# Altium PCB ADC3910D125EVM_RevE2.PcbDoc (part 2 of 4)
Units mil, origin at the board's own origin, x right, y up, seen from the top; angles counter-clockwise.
Board outline 4000 x 2716.54 mil, 6 copper layers (Top Layer, L2 GND, L3 PWR, L4 PWR, L5 GND, Bottom Layer), stack 60.99 mil thick; 318 components, 203 nets, 1298 pads, 559 vias.
Unrouted connection lines stored in the file: 5.
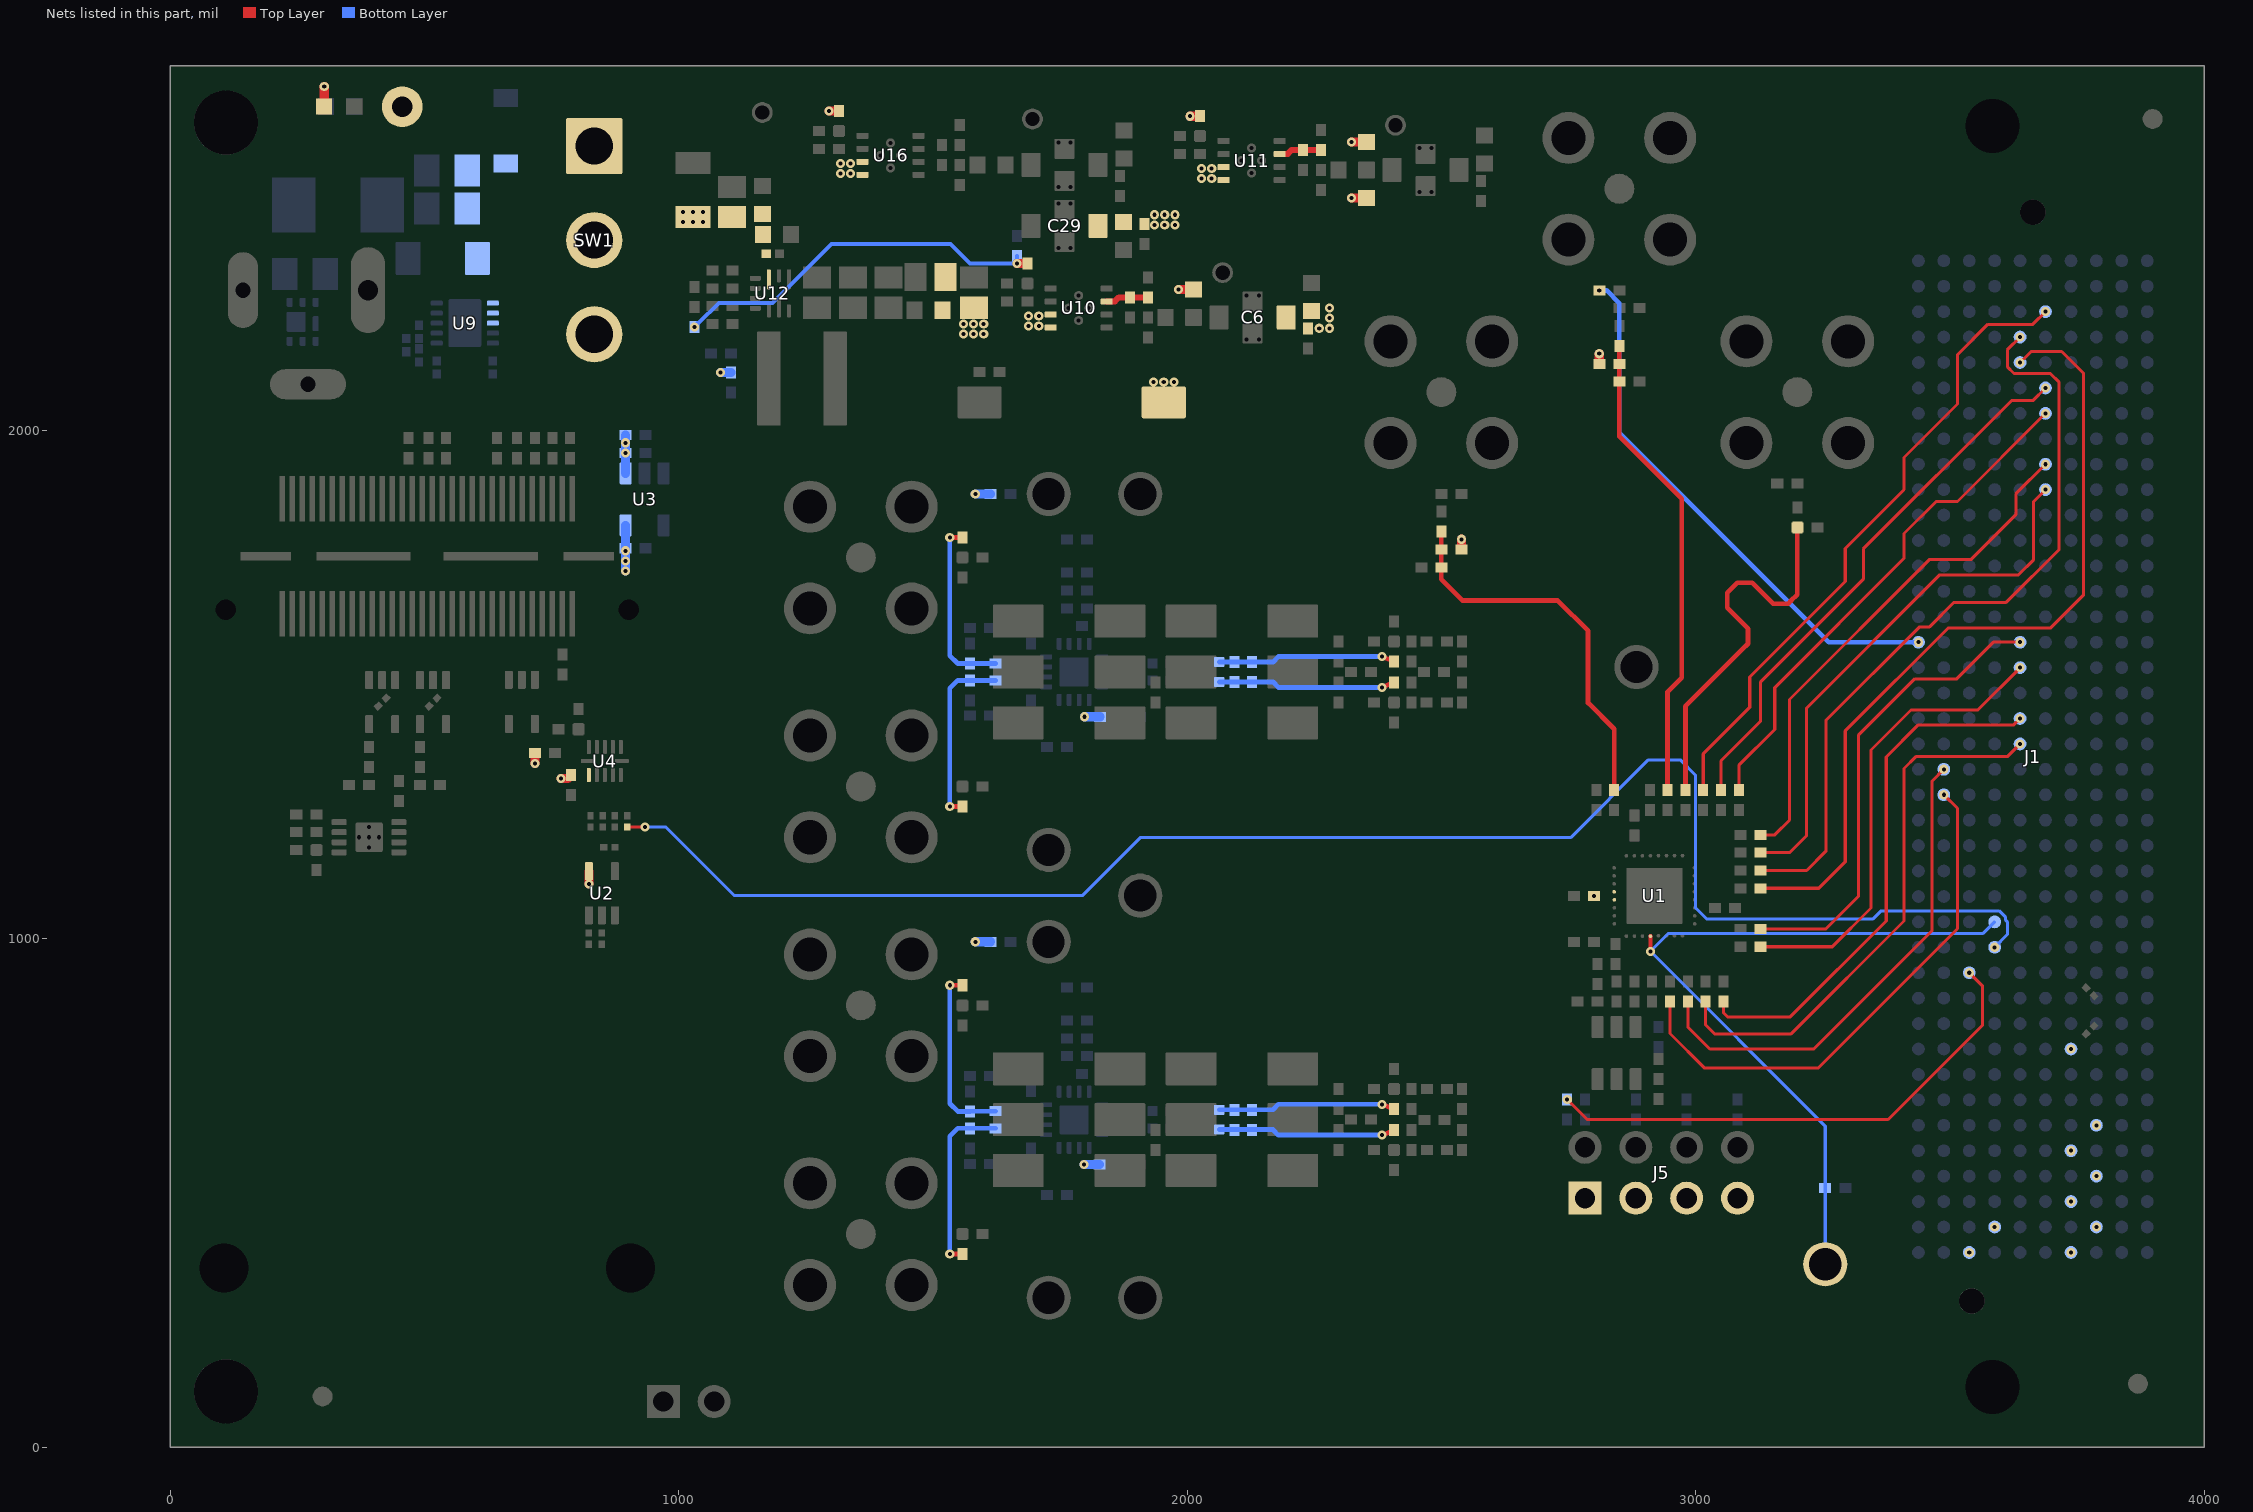
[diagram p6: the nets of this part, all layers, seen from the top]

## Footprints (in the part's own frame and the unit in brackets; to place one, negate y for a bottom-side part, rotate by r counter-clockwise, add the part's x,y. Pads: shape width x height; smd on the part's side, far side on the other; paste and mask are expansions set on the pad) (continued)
RSN0032B-MFG [mm]
  round 0.18 smd paste+0 mask+0: 1(-2.01,1.4) 2(-2.01,1) 3(-2.01,0.6) 4(-2.01,0.2) 5(-2,-0.2) 6(-2,-0.6) 7(-2,-1) 8(-2,-1.4) 9(-1.4,-2.01) 10(-1,-2.01) 11(-0.6,-2.01) 12(-0.2,-2.01) 13(0.2,-2) 14(0.6,-2) 15(1,-2) 16(1.4,-2) 17(2.01,-1.4) 18(2.01,-1) 19(2.01,-0.6) 20(2.01,-0.2) 21(2,0.2) 22(2,0.6) 23(2,1) 24(2,1.4) 25(1.4,2.01) 26(1,2.01) 27(0.6,2.01) 28(0.2,2.01) 29(-0.2,2) 30(-0.6,2) 31(-1,2) 32(-1.4,2)
  rrect4% 2.8x2.8 smd paste-1000 mask+0: 33(0,0)
  Top Layer region: -1.3,2.4 -1.3,1.7 -1.313,1.65 -1.35,1.613 -1.4,1.6 -1.4,1.6 -1.438,1.608 -1.471,1.629 -1.492,1.662 -1.5,1.7 -1.5,1.7 -1.5,2.4
  Top Layer region: -0.9,2.4 -0.9,1.7 -0.908,1.662 -0.929,1.629 -0.962,1.608 -1,1.6 -1,1.6 -1.038,1.608 -1.071,1.629 -1.092,1.662 -1.1,1.7 -1.1,1.7 -1.1,2.4
  Top Layer region: -0.5,2.4 -0.5,1.7 -0.508,1.662 -0.529,1.629 -0.562,1.608 -0.6,1.6 -0.6,1.6 -0.638,1.608 -0.671,1.629 -0.692,1.662 -0.7,1.7 -0.7,1.7 -0.7,2.4
  Top Layer region: -0.1,2.4 -0.1,1.7 -0.108,1.662 -0.129,1.629 -0.162,1.608 -0.2,1.6 -0.2,1.6 -0.238,1.608 -0.271,1.629 -0.292,1.662 -0.3,1.7 -0.3,1.7 -0.3,2.4
  Top Layer region: 0.3,2.4 0.3,1.7 0.292,1.662 0.271,1.629 0.238,1.608 0.2,1.6 0.2,1.6 0.162,1.608 0.129,1.629 0.108,1.662 0.1,1.7 0.1,1.7 0.1,2.4
  Top Layer region: 0.7,2.4 0.7,1.7 0.687,1.65 0.65,1.613 0.6,1.6 0.6,1.6 0.562,1.608 0.529,1.629 0.508,1.662 0.5,1.7 0.5,1.7 0.5,2.4
  Top Layer region: 1.1,2.4 1.1,1.7 1.092,1.662 1.071,1.629 1.038,1.608 1,1.6 1,1.6 0.962,1.608 0.929,1.629 0.908,1.662 0.9,1.7 0.9,1.7 0.9,2.4
  Top Layer region: 1.5,2.4 1.5,1.7 1.492,1.662 1.471,1.629 1.438,1.608 1.4,1.6 1.4,1.6 1.362,1.608 1.329,1.629 1.308,1.662 1.3,1.7 1.3,1.7 1.3,2.4
  Top Layer region: 1.3,-2.4 1.3,-1.7 1.308,-1.662 1.329,-1.629 1.362,-1.608 1.4,-1.6 1.4,-1.6 1.438,-1.608 1.471,-1.629 1.492,-1.662 1.5,-1.7 1.5,-1.7 1.5,-2.4
  Top Layer region: 0.9,-2.4 0.9,-1.7 0.908,-1.662 0.929,-1.629 0.962,-1.608 1,-1.6 1,-1.6 1.038,-1.608 1.071,-1.629 1.092,-1.662 1.1,-1.7 1.1,-1.7 1.1,-2.4
  Top Layer region: 0.5,-2.4 0.5,-1.7 0.508,-1.662 0.529,-1.629 0.562,-1.608 0.6,-1.6 0.6,-1.6 0.638,-1.608 0.671,-1.629 0.692,-1.662 0.7,-1.7 0.7,-1.7 0.7,-2.4
  Top Layer region: 0.1,-2.4 0.1,-1.7 0.108,-1.662 0.129,-1.629 0.162,-1.608 0.2,-1.6 0.2,-1.6 0.238,-1.608 0.271,-1.629 0.292,-1.662 0.3,-1.7 0.3,-1.7 0.3,-2.4
  Top Layer region: -0.3,-2.4 -0.3,-1.7 -0.292,-1.662 -0.271,-1.629 -0.238,-1.608 -0.2,-1.6 -0.2,-1.6 -0.162,-1.608 -0.129,-1.629 -0.108,-1.662 -0.1,-1.7 -0.1,-1.7 -0.1,-2.4
  Top Layer region: -0.7,-2.4 -0.7,-1.7 -0.692,-1.662 -0.671,-1.629 -0.638,-1.608 -0.6,-1.6 -0.6,-1.6 -0.562,-1.608 -0.529,-1.629 -0.508,-1.662 -0.5,-1.7 -0.5,-1.7 -0.5,-2.4
  Top Layer region: -1.1,-2.4 -1.1,-1.7 -1.092,-1.662 -1.071,-1.629 -1.038,-1.608 -1,-1.6 -1,-1.6 -0.962,-1.608 -0.929,-1.629 -0.908,-1.662 -0.9,-1.7 -0.9,-1.7 -0.9,-2.4
  Top Layer region: -1.5,-2.4 -1.5,-1.7 -1.492,-1.662 -1.471,-1.629 -1.438,-1.608 -1.4,-1.6 -1.4,-1.6 -1.362,-1.608 -1.329,-1.629 -1.308,-1.662 -1.3,-1.7 -1.3,-1.7 -1.3,-2.4
  Top Layer region: 2.4,1.3 1.7,1.3 1.662,1.308 1.629,1.329 1.608,1.362 1.6,1.4 1.6,1.4 1.608,1.438 1.629,1.471 1.662,1.492 1.7,1.5 1.7,1.5 2.4,1.5
  Top Layer region: 2.4,0.9 1.7,0.9 1.662,0.908 1.629,0.929 1.608,0.962 1.6,1 1.6,1 1.608,1.038 1.629,1.071 1.662,1.092 1.7,1.1 1.7,1.1 2.4,1.1
  Top Layer region: 2.4,0.5 1.7,0.5 1.662,0.508 1.629,0.529 1.608,0.562 1.6,0.6 1.6,0.6 1.608,0.638 1.629,0.671 1.662,0.692 1.7,0.7 1.7,0.7 2.4,0.7
  Top Layer region: 2.4,0.1 1.7,0.1 1.662,0.108 1.629,0.129 1.608,0.162 1.6,0.2 1.6,0.2 1.608,0.238 1.629,0.271 1.662,0.292 1.7,0.3 1.7,0.3 2.4,0.3
  Top Layer region: 2.4,-0.3 1.7,-0.3 1.662,-0.292 1.629,-0.271 1.608,-0.238 1.6,-0.2 1.6,-0.2 1.608,-0.162 1.629,-0.129 1.662,-0.108 1.7,-0.1 1.7,-0.1 2.4,-0.1
  Top Layer region: 2.4,-0.7 1.7,-0.7 1.662,-0.692 1.629,-0.671 1.608,-0.638 1.6,-0.6 1.6,-0.6 1.608,-0.562 1.629,-0.529 1.662,-0.508 1.7,-0.5 1.7,-0.5 2.4,-0.5
  Top Layer region: 2.4,-1.1 1.7,-1.1 1.662,-1.092 1.629,-1.071 1.608,-1.038 1.6,-1 1.6,-1 1.608,-0.962 1.629,-0.929 1.662,-0.908 1.7,-0.9 1.7,-0.9 2.4,-0.9
  Top Layer region: 2.4,-1.5 1.7,-1.5 1.662,-1.492 1.629,-1.471 1.608,-1.438 1.6,-1.4 1.6,-1.4 1.608,-1.362 1.629,-1.329 1.662,-1.308 1.7,-1.3 1.7,-1.3 2.4,-1.3
  Top Layer region: -2.4,-1.3 -1.7,-1.3 -1.662,-1.308 -1.629,-1.329 -1.608,-1.362 -1.6,-1.4 -1.6,-1.4 -1.613,-1.45 -1.65,-1.487 -1.7,-1.5 -1.7,-1.5 -2.4,-1.5
  Top Layer region: -2.4,-0.9 -1.7,-0.9 -1.662,-0.908 -1.629,-0.929 -1.608,-0.962 -1.6,-1 -1.6,-1 -1.608,-1.038 -1.629,-1.071 -1.662,-1.092 -1.7,-1.1 -1.7,-1.1 -2.4,-1.1
  Top Layer region: -2.4,-0.5 -1.7,-0.5 -1.662,-0.508 -1.629,-0.529 -1.608,-0.562 -1.6,-0.6 -1.6,-0.6 -1.608,-0.638 -1.629,-0.671 -1.662,-0.692 -1.7,-0.7 -1.7,-0.7 -2.4,-0.7
  Top Layer region: -2.4,-0.1 -1.7,-0.1 -1.662,-0.108 -1.629,-0.129 -1.608,-0.162 -1.6,-0.2 -1.6,-0.2 -1.608,-0.238 -1.629,-0.271 -1.662,-0.292 -1.7,-0.3 -1.7,-0.3 -2.4,-0.3
  Top Layer region: -2.4,0.3 -1.7,0.3 -1.662,0.292 -1.629,0.271 -1.608,0.238 -1.6,0.2 -1.6,0.2 -1.608,0.162 -1.629,0.129 -1.662,0.108 -1.7,0.1 -1.7,0.1 -2.4,0.1
  Top Layer region: -2.4,0.7 -1.7,0.7 -1.662,0.692 -1.629,0.671 -1.608,0.638 -1.6,0.6 -1.6,0.6 -1.608,0.562 -1.629,0.529 -1.662,0.508 -1.7,0.5 -1.7,0.5 -2.4,0.5
  Top Layer region: -2.4,1.1 -1.7,1.1 -1.662,1.092 -1.629,1.071 -1.608,1.038 -1.6,1 -1.6,1 -1.608,0.962 -1.629,0.929 -1.662,0.908 -1.7,0.9 -1.7,0.9 -2.4,0.9
  Top Layer region: -2.4,1.5 -1.7,1.5 -1.662,1.492 -1.629,1.471 -1.608,1.438 -1.6,1.4 -1.6,1.4 -1.608,1.362 -1.629,1.329 -1.662,1.308 -1.7,1.3 -1.7,1.3 -2.4,1.3
  silkscreen extent -3.1,-2.07 2.07,2.07, body extent -2.5,-2.5 2.5,2.5, height 0.25
RUT0012A [mm] "QFN, 12-Leads, Body 1.7x2mm, Pitch 0.4mm, TI Recommended"
  rrect50% 0.7x0.2 smd mask+0.05: 1(-0.7,0.8) 2(-0.7,0.4) 3(-0.7,0) 4(-0.7,-0.4) 5(-0.7,-0.8) 7(0.7,-0.8) 8(0.7,-0.4) 9(0.7,0) 10(0.7,0.4) 11(0.7,0.8)
  rrect50% 0.2x0.7 smd mask+0.05: 6(0,-0.85) 12(0,0.85)
  silkscreen extent -0.9,-1.2 0.9,1.2, body extent -0.85,-1 0.85,1, height 0.55
SAMTEC_ASP-134488-01 [mm]
  round 0.64 smd far side paste+0.125: A1(24.79,-5.715) A2(23.52,-5.715) A3(22.25,-5.715) A4(20.98,-5.715) A5(19.71,-5.715) A6(18.44,-5.715) A7(17.17,-5.715) A8(15.9,-5.715) A9(14.63,-5.715) A10(13.36,-5.715) A11(12.09,-5.715) A12(10.82,-5.715) A13(9.55,-5.715) A14(8.28,-5.715) A15(7.01,-5.715) A16(5.74,-5.715) A17(4.47,-5.715) A18(3.2,-5.715) A19(1.93,-5.715) A20(0.66,-5.715) A21(-0.61,-5.715) A22(-1.88,-5.715) A23(-3.15,-5.715) A24(-4.42,-5.715) A25(-5.69,-5.715) A26(-6.96,-5.715) A27(-8.23,-5.715) A28(-9.5,-5.715) A29(-10.77,-5.715) A30(-12.04,-5.715) A31(-13.31,-5.715) A32(-14.58,-5.715) A33(-15.85,-5.715) A34(-17.12,-5.715) A35(-18.39,-5.715) A36(-19.66,-5.715) A37(-20.93,-5.715) A38(-22.2,-5.715) A39(-23.47,-5.715) A40(-24.74,-5.715) B1(24.79,-4.445) B2(23.52,-4.445) B3(22.25,-4.445) B4(20.98,-4.445) B5(19.71,-4.445) B6(18.44,-4.445) B7(17.17,-4.445) B8(15.9,-4.445) B9(14.63,-4.445) B10(13.36,-4.445) B11(12.09,-4.445) B12(10.82,-4.445) B13(9.55,-4.445) B14(8.28,-4.445) B15(7.01,-4.445) B16(5.74,-4.445) B17(4.47,-4.445) B18(3.2,-4.445) B19(1.93,-4.445) B20(0.66,-4.445) B21(-0.61,-4.445) B22(-1.88,-4.445) B23(-3.15,-4.445) B24(-4.42,-4.445) B25(-5.69,-4.445) B26(-6.96,-4.445) B27(-8.23,-4.445) B28(-9.5,-4.445) B29(-10.77,-4.445) B30(-12.04,-4.445) B31(-13.31,-4.445) B32(-14.58,-4.445) B33(-15.85,-4.445) B34(-17.12,-4.445) B35(-18.39,-4.445) B36(-19.66,-4.445) B37(-20.93,-4.445) B38(-22.2,-4.445) B39(-23.47,-4.445) B40(-24.74,-4.445) C1(24.79,-3.175) C2(23.52,-3.175) C3(22.25,-3.175) C4(20.98,-3.175) C5(19.71,-3.175) C6(18.44,-3.175) C7(17.17,-3.175) C8(15.9,-3.175) C9(14.63,-3.175) C10(13.36,-3.175) C11(12.09,-3.175) C12(10.82,-3.175) C13(9.55,-3.175) C14(8.28,-3.175) C15(7.01,-3.175) C16(5.74,-3.175) C17(4.47,-3.175) C18(3.2,-3.175) C19(1.93,-3.175) C20(0.66,-3.175) C21(-0.61,-3.175) C22(-1.88,-3.175) C23(-3.15,-3.175) C24(-4.42,-3.175) C25(-5.69,-3.175) C26(-6.96,-3.175) C27(-8.23,-3.175) C28(-9.5,-3.175) C29(-10.77,-3.175) C30(-12.04,-3.175) C31(-13.31,-3.175) C32(-14.58,-3.175) C33(-15.85,-3.175) C34(-17.12,-3.175) C35(-18.39,-3.175) C36(-19.66,-3.175) C37(-20.93,-3.175) C38(-22.2,-3.175) C39(-23.47,-3.175) C40(-24.74,-3.175) D1(24.79,-1.905) D2(23.52,-1.905) D3(22.25,-1.905) D4(20.98,-1.905) D5(19.71,-1.905) D6(18.44,-1.905) D7(17.17,-1.905) D8(15.9,-1.905) D9(14.63,-1.905) D10(13.36,-1.905) D11(12.09,-1.905) D12(10.82,-1.905) D13(9.55,-1.905) D14(8.28,-1.905) D15(7.01,-1.905) D16(5.74,-1.905) D17(4.47,-1.905) D18(3.2,-1.905) D19(1.93,-1.905) D20(0.66,-1.905) D21(-0.61,-1.905) D22(-1.88,-1.905) D23(-3.15,-1.905) D24(-4.42,-1.905) D25(-5.69,-1.905) D26(-6.96,-1.905) D27(-8.23,-1.905) D28(-9.5,-1.905) D29(-10.77,-1.905) D30(-12.04,-1.905) D31(-13.31,-1.905) D32(-14.58,-1.905) D33(-15.85,-1.905) D34(-17.12,-1.905) D35(-18.39,-1.905) D36(-19.66,-1.905) D37(-20.93,-1.905) D38(-22.2,-1.905) D39(-23.47,-1.905) D40(-24.74,-1.905) E1(24.79,-0.635) E2(23.52,-0.635) E3(22.25,-0.635) E4(20.98,-0.635) E5(19.71,-0.635) E6(18.44,-0.635) E7(17.17,-0.635) E8(15.9,-0.635) E9(14.63,-0.635) E10(13.36,-0.635) E11(12.09,-0.635) E12(10.82,-0.635) E13(9.55,-0.635) E14(8.28,-0.635) E15(7.01,-0.635) E16(5.74,-0.635) E17(4.47,-0.635) E18(3.2,-0.635) E19(1.93,-0.635) E20(0.66,-0.635) E21(-0.61,-0.635) E22(-1.88,-0.635) E23(-3.15,-0.635) E24(-4.42,-0.635) E25(-5.69,-0.635) E26(-6.96,-0.635) E27(-8.23,-0.635) E28(-9.5,-0.635) E29(-10.77,-0.635) E30(-12.04,-0.635) E31(-13.31,-0.635) E32(-14.58,-0.635) E33(-15.85,-0.635) E34(-17.12,-0.635) E35(-18.39,-0.635) E36(-19.66,-0.635) E37(-20.93,-0.635) E38(-22.2,-0.635) E39(-23.47,-0.635) E40(-24.74,-0.635) F1(24.79,0.635) F2(23.52,0.635) F3(22.25,0.635) F4(20.98,0.635) F5(19.71,0.635) F6(18.44,0.635) F7(17.17,0.635) F8(15.9,0.635) F9(14.63,0.635) F10(13.36,0.635) F11(12.09,0.635) F12(10.82,0.635) F13(9.55,0.635) F14(8.28,0.635) F15(7.01,0.635) F16(5.74,0.635) F17(4.47,0.635) F18(3.2,0.635) F19(1.93,0.635) F20(0.66,0.635) F21(-0.61,0.635) F22(-1.88,0.635) F23(-3.15,0.635) F24(-4.42,0.635) F25(-5.69,0.635) F26(-6.96,0.635) F27(-8.23,0.635) F28(-9.5,0.635) F29(-10.77,0.635) F30(-12.04,0.635) F31(-13.31,0.635) F32(-14.58,0.635) F33(-15.85,0.635) F34(-17.12,0.635) F35(-18.39,0.635) F36(-19.66,0.635) F37(-20.93,0.635) F38(-22.2,0.635) F39(-23.47,0.635) F40(-24.74,0.635) G1(24.79,1.905) G2(23.52,1.905) G3(22.25,1.905) G4(20.98,1.905) G5(19.71,1.905) G6(18.44,1.905) G7(17.17,1.905) G8(15.9,1.905) G9(14.63,1.905) G10(13.36,1.905) G11(12.09,1.905) G12(10.82,1.905) G13(9.55,1.905) G14(8.28,1.905) G15(7.01,1.905) G16(5.74,1.905) G17(4.47,1.905) G18(3.2,1.905) G19(1.93,1.905) G20(0.66,1.905) G21(-0.61,1.905) G22(-1.88,1.905) G23(-3.15,1.905) G24(-4.42,1.905) G25(-5.69,1.905) G26(-6.96,1.905) G27(-8.23,1.905) G28(-9.5,1.905) G29(-10.77,1.905) G30(-12.04,1.905) G31(-13.31,1.905) G32(-14.58,1.905) G33(-15.85,1.905) G34(-17.12,1.905) G35(-18.39,1.905) G36(-19.66,1.905) G37(-20.93,1.905) G38(-22.2,1.905) G39(-23.47,1.905) G40(-24.74,1.905) H1(24.79,3.175) H2(23.52,3.175) H3(22.25,3.175) H4(20.98,3.175) H5(19.71,3.175) H6(18.44,3.175) H7(17.17,3.175) H8(15.9,3.175) H9(14.63,3.175) H10(13.36,3.175) H11(12.09,3.175) H12(10.82,3.175) H13(9.55,3.175) H14(8.28,3.175) H15(7.01,3.175) H16(5.74,3.175) H17(4.47,3.175) H18(3.2,3.175) H19(1.93,3.175) H20(0.66,3.175) H21(-0.61,3.175) H22(-1.88,3.175) H23(-3.15,3.175) H24(-4.42,3.175) H25(-5.69,3.175) H26(-6.96,3.175) H27(-8.23,3.175) H28(-9.5,3.175) H29(-10.77,3.175) H30(-12.04,3.175) H31(-13.31,3.175) H32(-14.58,3.175) H33(-15.85,3.175) H34(-17.12,3.175) H35(-18.39,3.175) H36(-19.66,3.175) H37(-20.93,3.175) H38(-22.2,3.175) H39(-23.47,3.175) H40(-24.74,3.175) J1(24.79,4.445) J2(23.52,4.445) J3(22.25,4.445) J4(20.98,4.445) J5(19.71,4.445) J6(18.44,4.445) J7(17.17,4.445) J8(15.9,4.445) J9(14.63,4.445) J10(13.36,4.445) J11(12.09,4.445) J12(10.82,4.445) J13(9.55,4.445) J14(8.28,4.445) J15(7.01,4.445) J16(5.74,4.445) J17(4.47,4.445) J18(3.2,4.445) J19(1.93,4.445) J20(0.66,4.445) J21(-0.61,4.445) J22(-1.88,4.445) J23(-3.15,4.445) J24(-4.42,4.445) J25(-5.69,4.445) J26(-6.96,4.445) J27(-8.23,4.445) J28(-9.5,4.445) J29(-10.77,4.445) J30(-12.04,4.445) J31(-13.31,4.445) J32(-14.58,4.445) J33(-15.85,4.445) J34(-17.12,4.445) J35(-18.39,4.445) J36(-19.66,4.445) J37(-20.93,4.445) J38(-22.2,4.445) J39(-23.47,4.445) J40(-24.74,4.445) K1(24.79,5.715) K2(23.52,5.715) K3(22.25,5.715) K4(20.98,5.715) K5(19.71,5.715) K6(18.44,5.715) K7(17.17,5.715) K8(15.9,5.715) K9(14.63,5.715) K10(13.36,5.715) K11(12.09,5.715) K12(10.82,5.715) K13(9.55,5.715) K14(8.28,5.715) K15(7.01,5.715) K16(5.74,5.715) K17(4.47,5.715) K18(3.2,5.715) K19(1.93,5.715) K20(0.66,5.715) K21(-0.61,5.715) K22(-1.88,5.715) K23(-3.15,5.715) K24(-4.42,5.715) K25(-5.69,5.715) K26(-6.96,5.715) K27(-8.23,5.715) K28(-9.5,5.715) K29(-10.77,5.715) K30(-12.04,5.715) K31(-13.31,5.715) K32(-14.58,5.715) K33(-15.85,5.715) K34(-17.12,5.715) K35(-18.39,5.715) K36(-19.66,5.715) K37(-20.93,5.715) K38(-22.2,5.715) K39(-23.47,5.715) K40(-24.74,5.715)
  round 0 hole 2.69 unplated: ""(-31.471,2.007) ""(31.521,2.007)
  round 1.27 hole 1.27 unplated: ""(-27.166,3.05) ""(27.216,0)
  body extent -27.86,-7.34 28.81,7.34, height 7.11
SMB-Bi [mil] "Molded Diode, 2-Leads, Body 5.4x3.6mm, IPC Medium Density, based on OnSemi component dimensions"
  rect 85x107.99 smd: 1(-87.01,0) 2(87.01,0)
  silkscreen extent -125,-79 125,79, body extent -104,-73 104,73, height 89
SOD-123 [mm] "On Semi recommended land pattern"
  rect 0.915x1.22 smd: 1(-1.637,0) 2(1.637,0)
  silkscreen extent -2.74,-1.17 2.03,1.17, body extent -1.93,-0.9 1.93,0.9, height 1.35
SPC02SYAN [mil] "SULLINS"
  round 1 on Mech3: 0(0,0)
  body extent -98,-47 99,47, height 366
TDFN8 [mm]
  rrect30% 0.75x0.3 smd paste+0 mask+0.05: 1(-1.5,0.75) 2(-1.5,0.25) 3(-1.5,-0.25) 4(-1.5,-0.75) 5(1.478,-0.75) 6(1.478,-0.25) 7(1.478,0.25) 8(1.478,0.75)
  round 0.327 / inner round 0.454 / far side round 0.454 hole 0.2 mask+0.05: 9(-0.5,0) 9(0,-0.5) 9(0,0) 9(0,0.5) 9(0.5,0)
  rrect10% 1.36x1.46 smd paste+0 mask+0.05: 9(0,0)
  silkscreen extent -2.23,0.67 -2.14,0.83, body extent -1.5,-1 1.5,1, height 0.76
TDK_IND_0402 [mm]
  rrect10% 0.5x0.5 smd paste+0 mask+0.05: 1(-0.45,0) 2(0.45,0)
  body extent -0.5,-0.3 0.5,0.3, height 0.5
TI_Stacked_Overlay_Small [mil]
  silkscreen extent -418,-98 418,98
XGL5030 [mm]
  rrect8% 1.18x4.7 smd paste+0 mask+0: 1(-1.655,0) 2(1.655,0)
  silkscreen extent -3.35,-2.84 2.74,2.84, body extent -2.84,-2.94 2.84,2.94, height 0.25

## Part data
C1 C7 C17 C27: library part capcc03298, "CAP CER 4.7UF 10V X5R 0402", Manufacturer="TDK Corporation", Operating Temperature="-55°C ~ 85°C", Ratings=-, Supplier Part Number 1=445-13820-1-ND, Temperature Coefficient=X5R, Tolerance=±10%, Voltage - Rated=10V
C2: library part capcc03230, "CAP CER 2.2UF 10V X5R 0402", Manufacturer="KYOCERA AVX", Operating Temperature="-55°C ~ 85°C", Ratings=-, Supplier Part Number 1=478-CM05X5R225K10AHCT-ND, Temperature Coefficient=X5R, Tolerance=±10%, Voltage - Rated=10V
C3 C4 C5 C9 C19 C33 C38 C42 C43 C44 C46 C48 C49 C50 C51 C52 C55 C68 C69 C70 C71 C72 C73 C78 C89 C90 C91 C92 C93 C94: library part capcc09401, "CAP CER 0.1UF 25V X7R 0402", Manufacturer=Murata, Operating Temperature="-55°C ~ 125°C", Ratings=-, Supplier Part Number 1=490-GRT155R71E104KE01JCT-ND, Temperature Coefficient=X7R, Tolerance=±10%, Voltage - Rated=25V
C6 C16 C21 C29: library part dcp00001, "Feed through capactior 27uF", Current=6A, Manufacturer=Murata, Operating Temperature="-40°C ~ 85°C", Supplier Part Number 1=490-6984-1-ND, Temperature Coefficient=-, Tolerance=±20%, Voltage - Rated=6.3V
C8 C18 C28 C32: library part capcc09400, "CAP CER 10UF 25V X5R 0603", Manufacturer=Murata, Operating Temperature="-55°C ~ 85°C", Ratings=-, Supplier Part Number 1=490-GRM188R61E106KA73JCT-ND, Temperature Coefficient=X5R, Tolerance=±10%, Voltage - Rated=25V
C10 C11 C12: library part CMP-0007730-2, "CAP, CERM, 1 uF, 50 V, +/- 10%, X7R, 0805", Cap_Case=0805, Manufacturer=Kemet, Supplier Part Number 1=399-7409-1-ND, TempCo=X7R, Tolerance_%=10%, Value1=Unknown, Value2=50V, ValueDisplayed=1uF
C13 C20 C40: library part capcc05563, "CAP CER 10000PF 10V X7R 0402", Manufacturer="KYOCERA AVX", Operating Temperature="-55°C ~ 125°C", Ratings=-, Supplier Part Number 1=478-0402ZC103JAT2ACT-ND, Temperature Coefficient=X7R, Tolerance=±5%, Voltage - Rated=10V
C14 C15: library part CMP-0009764-1, "CAP, CERM, 1000 pF, 25 V, +/- 10%, X7R, 0201", Cap_Case=0201, Manufacturer=MuRata, Supplier Part Number 1=490-3184-1-ND, TempCo=X7R, Tolerance_%=10%, Value1=Unknown, Value2=25V, ValueDisplayed=1000pF
C22: library part CMP-0008656-2, "CAP, CERM, 47 uF, 25 V, +/- 20%, X5R, 1206_190", Cap_Case=1206, Manufacturer=TDK, Supplier Part Number 1=445-8047-1-ND, TempCo=X5R, Tolerance_%=20%, Value1=Unknown, Value2=25V, ValueDisplayed=47uF
C23 C30 C31 C34 C35 C36: library part CMP-0008305-2, "CAP, CERM, 22 uF, 25 V, +/- 20%, X5R, 0805", Cap_Case=0805, Manufacturer=MuRata, Supplier Part Number 1=490-10749-1-ND, TempCo=X5R, Tolerance_%=20%, Value1=Unknown, Value2=25V, ValueDisplayed=22uF
C24 C25: library part CMP-0007007-5, "CAP, CERM, 10 uF, 25 V, +/- 20%, X5R, 0603", Cap_Case=0603, Manufacturer=TDK, Supplier Part Number 1=445-9015-1-ND, TempCo=X5R, Tolerance_%=20%, Value1="0.004639 ohm", Value2=25V, ValueDisplayed=10uF
C26: library part CMP-0009688-3, "CAP, CERM, 0.1 uF, 25 V, +/- 10%, X6S, 0201", Cap_Case=0201, Manufacturer=MuRata, Supplier Part Number 1=490-10403-1-ND, TempCo=X6S, Tolerance_%=10%, Value1=Unknown, Value2=25V, ValueDisplayed=0.1uF
C37 C39: library part CMP-0064928-2, "CAP, CERM, 0.47 uF, 25 V,+/- 10%, X5R, 0402", Cap_Case=0402, Manufacturer=MuRata, Supplier Part Number 1=490-14365-1-ND, TempCo=X5R, Tolerance_%=10%, Value1=Unknown, Value2=25V, ValueDisplayed=0.47uF
C45 C47: library part capcc02820, "CAP CER 1UF 10V X5R 0402", Manufacturer="KYOCERA AVX", Operating Temperature="-55°C ~ 85°C", Ratings=-, Supplier Part Number 1=478-4596-1-ND, Temperature Coefficient=X5R, Tolerance=±10%, Voltage - Rated=10V
C53 C54 C56 C57 C58 C59 C60 C63 C64 C65 C66 C67 C74 C75 C76 C77 C79 C80 C81 C82 C85 C86 C87 C88: library part capcc01284, "CAP CER 0.1UF 16V X7R 0402", Manufacturer="KYOCERA AVX", Operating Temperature="-55°C ~ 125°C", Ratings=-, Supplier Part Number 1=478-11502-1-ND, Temperature Coefficient=X7R, Tolerance=±5%, Voltage - Rated=16V
C61 C83: library part capcc06444, "CAP CER 180PF 50V X7R 0402", Manufacturer="KYOCERA AVX", Operating Temperature="-55°C ~ 125°C", Ratings=-, Supplier Part Number 1=478-1092-1-ND, Temperature Coefficient=X7R, Tolerance=±10%, Voltage - Rated=50V
C62 C84: library part capcc00002, "CAP CER 270PF 50V X7R 0402", Manufacturer="KYOCERA AVX", Operating Temperature="-55°C ~ 125°C", Ratings=-, Supplier Part Number 1=478-10124-1-ND, Temperature Coefficient=X7R, Tolerance=±5%, Voltage - Rated=50V
D1: library part CMP-0028547-2, "Diode, Schottky, 30 V, 1 A, SOD-123", Manufacturer="ON Semiconductor", Value1=1A, Value2=0.47V
D2: library part CMP-0006044-3, "Diode, TVS, Bi, 15 V, 24.4 Vc, SMB", Manufacturer="Fairchild Semiconductor", Value1=600W
D3: library part cmp00247, "LED GREEN CLEAR CHIP SMD", Alt Manufacturer=-, Color=Green, Current Rating (Amps)=20mA, Manufacturer="Lite-On Inc.", Supplier Part Number 1=160-1888-1-ND, Voltage - Forward (Vf) (Typ)=3.2V
F1: library part CMP-0095990-1, "1 A AC 63 V DC Fuse Board Mount (Cartridge Style Excluded) Surface Mount 1206 (3216 Metric)", Digikey Part Number=SF-1206FP100-2CT-ND, Fuse Current=1A, Fuse Interrupt Dc Current=50A, Manufacturer=Bourns, Mouser Part Number=652-SF-1206FP100-2, Operating Temperature Range="-20°C to +105°C"
FB1: library part dcp00379, "FERRITE BEAD", Current=8A, Manufacturer="Murata Electronics", Operating Temperature="-55°C ~ 125°C", Supplier Part Number 1=490-BLE18PS080SN1DCT-ND, Temperature Coefficient=-
FID1 FID2 FID3: library part cmp00099, "Fiducial", Alt Manufacturer=-
H1 H2: library part cmp00097, "Hex Standoff Threaded #4-40 Stainless Steel 1.250\" (31.75mm) 1 1/4", Alt Manufacturer=-, Manufacturer="RAF Electronic Hardware", Supplier Part Number 1=1772-1827-ND
H5 H6: library part cmp00358, "Hex Nut 3/16\" Stainless Steel 2-56", Alt Manufacturer=-, Manufacturer="B&F Fastener Supply", Supplier Part Number 1=H723-ND
J1: library part cmp00010, "EVM Connector 40x10", Alt Manufacturer=-, Manufacturer=Samtec, Supplier Part Number 1=SAM8730-ND
J2: library part cmp00061, "FTDI Dongle EVM Mating connector and standoff holes", Alt Manufacturer=-, Manufacturer=Samtec, Supplier Part Number 1=SAM8180-ND
J3: library part cmp00014, "Header, 100mil, 2x1, Gold, TH", Alt Manufacturer=-, Manufacturer="Sullins Connector Solutions", Supplier Part Number 1=S1011E-02-ND
J4: library part cmp00022, "Power Jack, mini, 2.1mm OD, R/A, TH", Alt Manufacturer=-, Manufacturer=Switchcraft, Supplier Part Number 1=SC1313-ND
J5: library part cmp00354, "Header, 100mil, 4x2, Gold, TH", Alt Manufacturer=-, Manufacturer="Sullins Connector Solutions", Supplier Part Number 1=S2011E-04-ND
J6 J7 J8 J9 J10 J11 J12: library part cmp00028, "SMA Connector Jack, Female Socket 50Ohm Surface Mount, Through Hole Solder", Alt Manufacturer=-, Manufacturer="Amphenol RF", Supplier Part Number 1=ACX1962-ND
L1: library part LSMT56800038, "POWER INDUCTOR, SHIELDED, COMPOS", Current - Saturation (Isat)=9.4A, Current Rating (Amps)="12.9 A", DC Resistance (DCR)="10.6m Ω", Frequency - Self Resonant=34MHz, Inductance Frequency - Test="1 MHz", Manufacturer=COILCRAFT, Operating Temperature="-40°C ~ 165°C", Package=XGL5030, Q @ Freq=-, Ratings=AEC-Q200
L2 L4 L6 L8: library part indrf00701, "FIXED IND 82NH 200MA 1.6 OHM SMD", Alternate Manufacturer=-, Current Rating="200 mA", DC Resistance (DCR)="1.6 Ω", Frequency - Self Resonant="700 MHz", Manufacturer="TDK Corporation", Operating Temperature="-55°C ~ 125°C", Package=0402, Q @ Freq="8 @ 100MHz", Supplier Part Number 1=445-3070-1-ND, Tolerance=±5%
L3 L5 L7 L9: library part indrf00703, "FIXED IND 330NH 50MA 7 OHM SMD", Alternate Manufacturer=-, Current Rating="50 mA", DC Resistance (DCR)="7 Ω", Frequency - Self Resonant="350 MHz", Manufacturer="TDK Corporation", Operating Temperature="-55°C ~ 125°C", Package=0402, Supplier Part Number 1=445-3077-1-ND, Tolerance=±5%
LBL1: library part CMP-0003625-1, "Thermal Transfer Printable Labels, 0.650\" W x 0.200\" H - 10,000 per roll", Manufacturer=Brady, Supplier Part Number 1=97C5133
Logo1: library part CMP-0074847-1, "FCC_disclaimer"
Logo2: library part cmp00104, "Texas Instrument Corporate Signature", Alt Manufacturer=-, PartNumber="TI Bug"
PP1 PP2 PP3 PP4: library part cmp00025, "Probe Point that can be used in lue of a test point", Alt Manufacturer=-
Q1: library part CMP-0000207-1, "MOSFET, N-CH, 20 V, 10 A, DQK0006C (WSON-6)", Alternate Manufacturer=None, Manufacturer="Texas Instruments", Supplier Part Number 1=CSD15571Q2-ND, Value1=19, Value2="2.5 nC"
R1 R2 R4 R5 R6 R7 R9 R21 R27: library part RSMD020101699, "RES SMD 0 OHM JUMPER 1/20W 0201", Manufacturer="Panasonic Electronic Components", Operating Temperature="-55°C ~ 125°C", Power (Watts)="0.05W, 1/20W", Resistance="0 Ω", Supplier Part Number 1=P15979CT-ND, Tolerance=Jumper
R3 R32 R35 R36 R42 R44 R45 R47 R48 R50 R68 R70 R74 R136 R137 R138 R139 R144 R146 R147: library part RSMD040200314, "RES SMD 10K OHM 1% 1/10W 0402", Manufacturer="Panasonic Electronic Components", Operating Temperature="-55°C ~ 155°C", Power (Watts)="0.1W, 1/10W", Ratings=AEC-Q200, Resistance="10 kΩ", Supplier Part Number 1=P10.0KLCT-ND, Temperature Coefficient=±100ppm/°C, Tolerance=±1%
R8 R10 R11 R12 R13 R14 R15 R16 R17 R18 R23 R29 R66 R69 R72 R73 R75 R76 R77 R78 R80 R83 R89 R90 R91 R98 R102 R103 R104 R106 R107 R112 R113 R114 R122 R125 R126 R127 R129 R130 R140 R143: library part RSMD040200001, "RES SMD 0 OHM JUMPER 1/10W 0402", Manufacturer="Panasonic Electronic Components", Operating Temperature="-55°C ~ 155°C", Power (Watts)="0.1W, 1/10W", Ratings=AEC-Q200, Resistance="0 Ω", Supplier Part Number 1=P0.0JCT-ND, Temperature Coefficient=-, Tolerance=Jumper
R19 R20 R24 R25 R26 R105 R128: library part RSMD040200306, "RES SMD 10K OHM 5% 1/10W 0402", Manufacturer="Panasonic Electronic Components", Operating Temperature="-55°C ~ 155°C", Power (Watts)="0.1W, 1/10W", Ratings=AEC-Q200, Resistance="10 kΩ", Supplier Part Number 1=P10KJCT-ND, Temperature Coefficient=±200ppm/°C, Tolerance=±5%
R22 R28: library part RSMD040201206, "RES SMD 2.2K OHM 5% 1/10W 0402", Manufacturer="Panasonic Electronic Components", Operating Temperature="-55°C ~ 155°C", Power (Watts)="0.1W, 1/10W", Ratings=AEC-Q200, Resistance="2.2 kΩ", Supplier Part Number 1=P2.2KJCT-ND, Temperature Coefficient=±200ppm/°C, Tolerance=±5%
R30 R31 R39 R40 R41 R142: library part RSMD060312253, "RES 0 OHM JUMPER 0603 SMD", Manufacturer="Panasonic Electronic Components", Operating Temperature="-55°C ~ 155°C", Power (Watts)="0.1W, 1/10W", Ratings=AEC-Q200, Resistance="0 Ω", Supplier Part Number 1=10-ERJ-U030R00VCT-ND, Temperature Coefficient=±200ppm/°C, Tolerance=Jumper
R33 R43: library part RSMD040202026, "RES SMD 12.7K OHM 1% 1/10W 0402", Manufacturer="Panasonic Electronic Components", Operating Temperature="-55°C ~ 155°C", Package / Case=0402, Power (Watts)="0.1W, 1/10W", Ratings=AEC-Q200, Temperature Coefficient=±100ppm/°C, Tolerance=±1%
R34: library part CMP-0027059-1, "RES, 1.0 M, 5%, 0.05 W, 0201", Manufacturer="Yageo America", Power_W=50mW, Supplier Part Number 1=311-1MNCT-ND, TempCo="200 ppm/C", Tolerance_%=5%, Value2=0.05W, Value_Code=1M00, ValueDisplayed=1.0M
R37: library part CMP-0028019-1, "RES, 45.3 k, 1%, 0.05 W, 0201", Manufacturer="Yageo America", Power_W=50mW, Supplier Part Number 1=603-RC0201FR-7D45K3L, TempCo="200 ppm/C", Tolerance_%=1%, Value2=0.05W, Value_Code=45k3, ValueDisplayed=45.3k
R38: library part CMP-0028107-1, "RES, 4.99 k, 1%, 0.05 W, 0201", Manufacturer="Yageo America", Power_W=50mW, Supplier Part Number 1=603-RC0201FS-7D4K99L, TempCo="200 ppm/C", Tolerance_%=1%, Value2=0.05W, Value_Code=4k99, ValueDisplayed=4.99k
R46: library part RSMD060304038, "RES 15K OHM 1% 1/4W 0603", Manufacturer="Panasonic Electronic Components", Operating Temperature="-55°C ~ 155°C", Power (Watts)="0.25W, 1/4W", Ratings=AEC-Q200, Resistance="15 kΩ", Supplier Part Number 1=10-ERJ-UP3F1502VCT-ND, Temperature Coefficient=±100ppm/°C, Tolerance=±1%
R49: library part CMP-0026992-3, "RES, 0, 5%, 0.1 W, AEC-Q200 Grade 0, 0402", Manufacturer=Panasonic, Power_W=100mW, Supplier Part Number 1=P0.0JCT-ND, TempCo="600 ppm/C", Tolerance_%=5%, Value2=0.1W, Value_Code=0000, ValueDisplayed=0
R51: library part RSMD040200251, "RES SMD 18.2 OHM 1% 1/10W 0402", Manufacturer="Panasonic Electronic Components", Operating Temperature="-55°C ~ 155°C", Package / Case=0402, Power (Watts)="0.1W, 1/10W", Ratings=AEC-Q200, Temperature Coefficient=±100ppm/°C, Tolerance=±1%
R52: library part RSMD040201128, "RES SMD 19.6K OHM 1% 1/10W 0402", Manufacturer="Panasonic Electronic Components", Operating Temperature="-55°C ~ 155°C", Power (Watts)="0.1W, 1/10W", Ratings=AEC-Q200, Resistance="19.6 kΩ", Supplier Part Number 1=P19.6KLCT-ND, Temperature Coefficient=±100ppm/°C, Tolerance=±1%
R53: library part RSMD040201711, "RES SMD 4.87K OHM 1% 1/10W 0402", Manufacturer="Panasonic Electronic Components", Operating Temperature="-55°C ~ 155°C", Package / Case=0402, Power (Watts)="0.1W, 1/10W", Ratings=AEC-Q200, Temperature Coefficient=±100ppm/°C, Tolerance=±1%
R54 R55 R56 R57 R58 R59 R60 R61 R62 R63 R64 R65 R67 R71: library part RSMD040200375, "RES SMD 100 OHM 1% 1/10W 0402", Manufacturer="Panasonic Electronic Components", Operating Temperature="-55°C ~ 155°C", Power (Watts)="0.1W, 1/10W", Ratings=AEC-Q200, Resistance="100 Ω", Supplier Part Number 1=P100LCT-ND, Temperature Coefficient=±100ppm/°C, Tolerance=±1%
R79: library part RSMD040200006, "RES SMD 1K OHM 1% 1/10W 0402", Manufacturer="Panasonic Electronic Components", Operating Temperature="-55°C ~ 155°C", Power (Watts)="0.1W, 1/10W", Ratings=AEC-Q200, Resistance="1 kΩ", Supplier Part Number 1=P1.00KLCT-ND, Temperature Coefficient=±100ppm/°C, Tolerance=±1%
R81 R82 R86 R87 R92 R101 R115 R120: library part RSMD040200016, "RES SMD 1K OHM 0.1% 1/16W 0402", Manufacturer="Panasonic Electronic Components", Operating Temperature="-55°C ~ 155°C", Power (Watts)="0.063W, 1/16W", Ratings=AEC-Q200, Resistance="1 kΩ", Supplier Part Number 1=P1KCPCT-ND, Temperature Coefficient=±10ppm/°C, Tolerance=±0.1%
R84 R85 R93 R97 R116 R119 R141: library part RSMD040202911, "RES SMD 49.9 OHM 1% 1/10W 0402", Manufacturer="Panasonic Electronic Components", Operating Temperature="-55°C ~ 155°C", Power (Watts)="0.1W, 1/10W", Ratings=AEC-Q200, Resistance="49.9 Ω", Supplier Part Number 1=P49.9LCT-ND, Temperature Coefficient=±100ppm/°C, Tolerance=±1%
R88 R96 R110 R111 R121 R133: library part RSMD040202923, "RES SMD 499 OHM 1% 1/10W 0402", Manufacturer="Panasonic Electronic Components", Operating Temperature="-55°C ~ 155°C", Power (Watts)="0.1W, 1/10W", Ratings=AEC-Q200, Resistance="499 Ω", Supplier Part Number 1=P499LCT-ND, Temperature Coefficient=±100ppm/°C, Tolerance=±1%
R94 R99 R117 R123: library part RSMD040201387, "RES SMD 200 OHM 1% 1/10W 0402", Manufacturer="Panasonic Electronic Components", Operating Temperature="-55°C ~ 155°C", Power (Watts)="0.1W, 1/10W", Ratings=AEC-Q200, Resistance="200 Ω", Supplier Part Number 1=P200LCT-ND, Temperature Coefficient=±100ppm/°C, Tolerance=±1%
R95 R100 R118 R124: library part RSMD040202422, "RES SMD 37.4 OHM 1% 1/10W 0402", Manufacturer="Panasonic Electronic Components", Operating Temperature="-55°C ~ 155°C", Power (Watts)="0.1W, 1/10W", Ratings=AEC-Q200, Resistance="37.4 Ω", Supplier Part Number 1=P37.4LCT-ND, Temperature Coefficient=±100ppm/°C, Tolerance=±1%
R108 R109 R131 R132: library part RSMD040201785, "RES SMD 27 OHM 1% 1/10W 0402", Manufacturer="Panasonic Electronic Components", Operating Temperature="-55°C ~ 155°C", Power (Watts)="0.1W, 1/10W", Ratings=AEC-Q200, Resistance="27 Ω", Supplier Part Number 1=P27.0LCT-ND, Temperature Coefficient=±100ppm/°C, Tolerance=±1%
R134 R135: library part CMP-0027008-4, "RES, 0, 5%, 0.05 W, 0201", Manufacturer=Vishay-Dale, Power_W=50mW, Supplier Part Number 1=72M6743, TempCo=ppm/C, Tolerance_%=5%, Value2=0.05W, Value_Code=0000, ValueDisplayed=0
R145: library part RSMD040202088, "RES SMD 30.9K OHM 1% 1/10W 0402", Manufacturer="Panasonic Electronic Components", Operating Temperature="-55°C ~ 155°C", Power (Watts)="0.1W, 1/10W", Ratings=AEC-Q200, Resistance="30.9 kΩ", Supplier Part Number 1=P30.9KLCT-ND, Temperature Coefficient=±100ppm/°C, Tolerance=±1%
SH-J1: library part cmp00093, "2 (1 x 2) Position Shunt Connector Black Closed Top 0.100\" (2.54mm) Gold", Alt Manufacturer=-, Manufacturer=Sullins, Supplier Part Number 1=S9001-ND
SW1: library part cmp00021, "Switch Slide SPDT 120V, 6A", Alt Manufacturer=-, Manufacturer="C&K Components", Supplier Part Number 1=CKN9628-ND
SW2: library part cmp00234, "SWITCH TACTILE SPST-NO 0.05A 24V", Alt Manufacturer=-, Manufacturer="TE Connectivity", Supplier Part Number 1=A101402CT-ND
T1 T2 T3 T4: library part CMP-0089317-2, "RF Transformer Surface Mount 50Ω 4.5 to 3000 MHz", Frequency_Fixed=0.4-450MHz, Manufacturer=Mini-Circuits, Mouser Part Number=139-ADT2-1T, Operating Temperature Range="-20°C to +85°C"
TP3: library part connector00030, "Test Point, Miniature, Red, TH", Color=Red, Manufacturer=Keystone
TP4 TP5 TP6: library part cmp00041, "Test Point, Multipurpose, Black, TH", Alt Manufacturer=-, Color=Black, Manufacturer=Keystone, Supplier Part Number 1=36-5011-ND
TP7 TP8: library part cmp00043, "Test Point, Multipurpose, Orange, TH", Alt Manufacturer=-, Color=Orange, Manufacturer=Keystone, Supplier Part Number 1=36-5013-ND
TP9 TP11: library part cmp00049, "Test Point, Multipurpose, Purple, TH", Alt Manufacturer=-, Color=Purple, Manufacturer=Keystone, Supplier Part Number 1=36-5129-ND
TP10 TP12: library part cmp00040, "Test Point, Multipurpose, Red, TH", Alt Manufacturer=-, Color=Red, Manufacturer=Keystone, Supplier Part Number 1=36-5010-ND
U1: library part CMP-0095180-2, Manufacturer="Texas Instruments", Operating Temperature Range=to
U2 U5 U7 U8: library part cmp00143, "Single Bus Buffer Gate With 3-State Outputs", Alt Manufacturer=-, Manufacturer="Texas Instruments"
U3: library part cmp00355, "150-mA, 30-V, ultra-low-IQ, low-dropout voltage regulator with reverse current protection and enable", Alt Manufacturer="Texas Instruments", Alt PartNumber=TPS70918DBVT, Color=-
U4: library part cmp00182, "4-Bit Bidirectional Multi-Voltage Level Translator for Open-Drain & Push- Pull", Alt Manufacturer="Texas Instruments", Color=-, Supplier Part Number 1=296-40404-1-ND
U6: library part cmp00154, "EEPROM 64K 8KX8 1.8V SER EE IND 1/4AWP RPO", Alt Manufacturer=-, Manufacturer=Microchip, Supplier Part Number 1=24LC64FT-I/MNYCT-ND
U9: library part CMP-0074225-5, "12V, 5A, 30mΩ eFuse with Adjustable +/-15% Accurate Current Limit, DRC0010J (VSON-10)", Alternate Manufacturer="Texas Instruments", Alternate PartNumber=TPS259261DRCT, Operating Temperature Range="-40 to 85 C", Rating=Catalog
U10 U11 U16: library part cmp00168, "1-A, high-PSRR, ultra-low-dropout voltage regulator with low-IQ & enable", Alt Manufacturer=-, Manufacturer="Texas Instruments"
U12: library part CMP-0860321-2, "3A Low Noise and Low Ripple buck converter, RPU0010A (VQFN-10)", Alternate Manufacturer="Texas Instruments"
U13: library part cmp00301, "Ultra Low-Power, High-Precision Voltage Reference", Alt Manufacturer=-, Manufacturer="Texas Instruments", PartNumber=REF35160QDBV
U14 U15: library part CMP-0065559-3, "High-Speed Differential I/O Amplifier, RGT0016A (VQFN-16)", Alternate Manufacturer="Texas Instruments", Alternate PartNumber=THS4541IRGTT
ZZ1: library part CMP-0003616-3
ZZ2: library part CMP-0077236-1
ZZ3: library part CMP-0077237-1
ZZ4: library part CMP-0077238-1

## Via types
v1: diameter 18, hole 8, Top Layer to Bottom Layer, tented both sides, 546 vias
v2: diameter 23.62, hole 11.81, Top Layer to Bottom Layer, tented both sides, 9 vias
v3: diameter 19.68, hole 7.87, Top Layer to Bottom Layer, tented both sides, 4 vias

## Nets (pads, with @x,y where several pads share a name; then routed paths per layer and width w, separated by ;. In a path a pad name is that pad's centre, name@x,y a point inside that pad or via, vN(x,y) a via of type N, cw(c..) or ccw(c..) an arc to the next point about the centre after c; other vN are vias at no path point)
4V_LDO: C30.1 C31.1 FB1.2 R32.2 R42.2 R47.2 R49.2 R144.2 U10.7 U10.8 U11.7 U11.8 U16.7 U16.8 | length 793.7
  Top Layer w18: v1(1295.76,2627.68) R144.2@1315.76,2627.68 ; v1(1665.76,2327.68) R32.2@1685.76,2327.68 ; v1(2005.76,2617.68) R42.2@2025.76,2617.68
  Bottom Layer w8: v1(1031.68,2202.87) 1031.68,2204.84 1037.52,2210.68 1039.49,2210.68 1079.27,2250.47 1184.9,2250.47 1300.46,2366.03 1535,2366.03 1573.35,2327.68 v1(1665.76,2327.68) R47.2@1665.76,2342.68
  other v1: 1560.11,2189.22 1580.11,2189.22 1600.11,2189.22 1688.43,2204.8 1708.43,2204.8 1560.11,2209.22 1580.11,2209.22 1600.11,2209.22 1688.43,2224.8 1708.43,2224.8 2028.43,2494.8 2048.43,2494.8 1318.42,2504.8 1338.42,2504.8 2028.43,2514.8 2048.43,2514.8 1318.42,2524.8 1338.42,2524.8
+1.8V_FTDI: C2.2 C4.2 R19.2 U2.5 U3.5 U4.1 | length 158.5
  Top Layer w18: v1(717.48,1345) R19.2@717.48,1365 ; v1(768.79,1315.56) 782.09,1315.56 785.69,1319.16 787.66,1319.16 788.5,1320 C4.2@788.5,1321.97 ; v1(823.69,1107.87) U2.5@823.69,1132.87
  Bottom Layer w18: v1(895.95,1723.01) C2.2@895.95,1768.01 U3.5@895.95,1813.01
  other v1: 895.95,1743.01 895.95,1763.01
+12V: C1.2 C22.1 C23.1 C24.1 C25.1 C26.1 D3.1 R3.2 R48.2 SW1.2 TP3.1 U3.1 U12.6 | length 135
  Top Layer w18: D3.1@303.22,2636.35 v1(303.22,2676.35)
  Bottom Layer w18: U3.1@895.95,1915.37 v1(895.95,1955.37) R3.2@895.95,1990.37 ; v1(1082.82,2113.39) R48.2@1102.82,2113.39
  other v1: 895.95,1975.37 1008.44,2409.65 1028.44,2409.65 1048.44,2409.65 1008.44,2429.65 1028.44,2429.65 1048.44,2429.65
+12V_JACK: C11.1 C12.1 D1.1 F1.2 SW1.1 U9.6 U9.7 U9.8
ALERT/GPO: J1.G27 R70.1 TP8.1 U1.20 | length 1488.6
  Top Layer w8: v1(2911.27,975.34) U1.20@2911.27,1005.34
  Bottom Layer w6: TP8.1@3255,360 R70.1@3255,510 3255,631.61 v1(2911.27,975.34) 2946.6,1010.67 3565.59,1010.67 J1.G27@3588.19,1033.27
AMP_INAM: C53.2 R99.1 R108.2 | length 353.7
  Top Layer w9.5: v1(1533.43,1789.07) C53.2@1558.43,1789.07
  Bottom Layer w9.5: v1(1533.43,1789.07) 1533.43,1556.82 1548.9,1541.34 R108.2@1573.47,1541.34 ; R108.2@1573.47,1541.69 R99.1@1623.47,1541.69
AMP_INAP: C66.1 R94.1 R109.2 | length 353.7
  Top Layer w9.5: v1(1533.43,1260.33) C66.1@1558.43,1260.33
  Bottom Layer w9.5: v1(1533.43,1260.33) 1533.43,1492.58 1548.91,1508.06 R109.2@1573.47,1508.06 R94.1@1623.47,1508.06
AMP_INBM: C74.2 R123.1 R131.2 | length 353.7
  Top Layer w9.5: v1(1533.43,908.66) C74.2@1558.43,908.66
  Bottom Layer w9.5: v1@1533.43,908.31 1533.43,676.05 1548.9,660.58 R131.2@1573.47,660.58 ; R131.2@1573.48,660.92 R123.1@1623.48,660.92
AMP_INBP: C88.1 R117.1 R132.2 | length 353.7
  Top Layer w9.5: v1(1533.43,379.92) C88.1@1558.43,379.92
  Bottom Layer w9.5: v1@1533.43,379.57 1533.43,611.82 1548.91,627.3 R132.2@1573.48,627.3 R117.1@1623.48,627.3
AMP_OUT_AM: C62.1 L5.2 R89.2 R96.1 | length 349.7
  Top Layer w9.5: v1(2383.61,1554.9) R89.2@2406.71,1545.33
  Bottom Layer w9.5: L5.2@2063.32,1544.21 2093.32,1544.21 2127.32,1544.21 2168.97,1544.21 2179.66,1554.9 v1(2383.61,1554.9)
AMP_OUT_AP: C62.2 L3.2 R96.2 R104.2 | length 349.7
  Top Layer w9.5: v1(2383.61,1494.5) R104.2@2406.71,1504.07
  Bottom Layer w9.5: L3.2@2063.32,1505.19 C62.2@2093.32,1505.19 R96.2@2127.32,1505.19 2168.97,1505.19 2179.66,1494.5 v1(2383.61,1494.5)
AMP_OUT_BM: C84.1 L9.2 R112.2 R121.1 | length 349.7
  Top Layer w9.5: v1(2383.61,674.49) R112.2@2406.71,664.92
  Bottom Layer w9.5: L9.2@2063.32,663.8 C84.1@2093.32,663.8 R121.1@2127.32,663.8 2168.97,663.8 2179.66,674.49 v1(2383.61,674.49)
AMP_OUT_BP: C84.2 L7.2 R121.2 R127.1 | length 349.7
  Top Layer w9.5: v1(2383.61,614.09) R127.1@2406.71,623.66
  Bottom Layer w9.5: L7.2@2063.32,624.78 2093.32,624.78 2127.32,624.78 2168.97,624.78 2179.66,614.09 v1(2383.61,614.09)
AVDD: C6.3 C8.2 C9.2 C42.2 C43.2 J5.1 J5.3 J5.5 J5.7 R81.2 R82.2 SW2.1 U1.12 U1.13 | length 40
  Top Layer w18: R82.2@2539.37,1765.63 v1(2539.37,1785.63) ; R81.2@2810.63,2130.63 v1(2810.63,2150.63)
  other v1: 2800.4,1084.49 1934.16,2095 1954.16,2095 1974.16,2095 2260,2200.51 2280,2200.51 2280,2220.51 2280,2240.51
CLK: C52.1 R69.1 R82.1 R87.2 | length 758.1
  Top Layer w9.5: C52.1@2500,1800.63 R82.1@2500,1765.63 R87.2@2500,1730.63 2500,1707.18 2541.98,1665.2 2729.1,1665.2 2788.59,1605.71 2788.59,1463.99 2840.06,1412.52 R69.1@2840.06,1293.01
D00: R54.2 R140.2 R143.1 | length 758.1
  Top Layer w9.5: R54.2@2980.06,1293.01 2980.06,1457.02 3100,1576.96 3103.36,1580.32 3103.36,1609.81 3062.15,1651.01 3062.15,1680.5 3081.81,1700.16 3111.29,1700.16 3152.5,1658.95 3181.99,1658.95 3187.5,1664.46 3200,1676.96 3200,1738.9 3200,1773.9 R140.2@3200,1808.9
D01: J1.E3 R55.2 | length 1270.9
  Top Layer w6: R55.2@3015.06,1293.01 3015.06,1363.61 3106.59,1455.14 3106.59,1514.86 3294.37,1702.64 3294.37,1767.64 3410,1883.27 3410,1946.64 3515,2051.64 3515,2148.62 3574.65,2208.27 3663.19,2208.27 v1(3688.19,2233.27)
D02: J1.E6 R56.2 | length 1079
  Top Layer w6: R56.2@3050.06,1293.01 3050.06,1350.06 3127.25,1427.25 3127.25,1504.43 3330,1707.18 3330,1766.81 3621.46,2058.27 3663.19,2058.27 v1(3688.19,2083.27)
D03: J1.E7 R57.2 | length 1014.6
  Top Layer w6: R57.2@3085.06,1293.01 3085.06,1341.08 3155.69,1411.71 3155.69,1493.96 3410,1748.27 3410,1796.9 3473.1,1860 3514.92,1860 v1(3688.19,2033.27)
D04: J1.E9 R58.2 | length 1025.9
  Top Layer w6: R58.2@3127.25,1204.36 3155.69,1204.36 3184.6,1233.27 3184.6,1470.73 3459.42,1745.55 3541.38,1745.55 3629.92,1834.09 3629.92,1875 v1(3688.19,1933.27)
D05: J1.E10 R59.2 | length 1070.6
  Top Layer w6: R59.2@3127.25,1169.36 3184.6,1169.36 3218.47,1203.23 3218.47,1454.03 3480.07,1715.63 3635,1715.63 3664.92,1745.55 3664.92,1860 v1(3688.19,1883.27)
D06: J1.F16 R60.2 | length 930
  Top Layer w6: R60.2@3127.25,1019.36 3256.09,1019.36 3320,1083.27 3320,1400 3431.26,1511.26 3513.65,1511.26 3585.66,1583.27 v1(3638.19,1583.27)
D07: J1.F17 R61.2 | length 920.5
  Top Layer w6: R61.2@3127.25,984.36 3268.88,984.36 3345,1060.48 3345,1371.44 3423.63,1450.06 3554.98,1450.06 v1(3638.19,1533.27)
D08: J1.F19 R62.2 | length 1040.8
  Top Layer w6: R62.2@3054.77,876.38 3054.77,854.31 3062.64,846.44 3186.44,846.44 3375,1035 3375,1357.56 3438.19,1420.75 3625.67,1420.75 v1(3638.19,1433.27)
D09: J1.F20 R63.2 | length 1083.6
  Top Layer w6: R63.2@3019.77,876.38 3019.77,830.32 3037.11,812.98 3187.98,812.98 3410,1035 3410,1335 3433.27,1358.27 3613.19,1358.27 v1(3638.19,1383.27)
D10: J1.J21 R64.2 | length 971.5
  Top Layer w6: R64.2@2984.77,876.38 2984.77,826.43 3027.93,783.27 3232.62,783.27 3465,1015.65 3465,1310.08 v1(3488.19,1333.27)
D11: J1.J22 R65.2 | length 1044
  Top Layer w6: R65.2@2949.77,876.38 2949.77,813.86 3018,745.63 3240.63,745.63 3515,1020 3515,1256.46 v1(3488.19,1283.27)
"D\C\L\K\ /FCLK": J1.F5 R71.2 | length 1613
  Top Layer w6: R71.2@3127.25,1099.36 3242.31,1099.36 3294.37,1151.42 3294.37,1408.89 3496.29,1610.81 3697.54,1610.81 3763.19,1676.46 3763.19,2111.81 3720,2155 3659.92,2155 v1(3638.19,2133.27)
DCLK: J1.F4 R67.2 | length 1511.6
  Top Layer w6: R67.2@3127.25,1134.36 3218.47,1134.36 3256.09,1171.99 3256.09,1429.1 3437.8,1610.81 3438.19,1610.81 3440.89,1613.52 3460.32,1613.52 3508.36,1661.56 3610.83,1661.56 3715,1765.73 3715,2094.36 3697.54,2111.81 3626.37,2111.81 3613.19,2125 3613.19,2158.27 v1(3638.19,2183.27)
DCLKIN: C51.1 R72.1 R81.1 R86.2 | length 934.9
  Top Layer w9.5: C51.1@2850,2165.63 R81.1@2850,2130.63 R86.2@2850,2095.63 2850,1987.93 2972.76,1865.17 2972.76,1513.37 2945.06,1485.68 R72.1@2945.06,1293.01
FB1: R33.1 R36.2 U10.3 | length 84.3
  Top Layer w12: U10.3@1841.99,2253.31 1842.09,2253.41 1857.93,2253.41 1865.9,2261.38 R33.1@1887.99,2261.38 R36.2@1922.99,2261.38
FB2: R43.1 R45.2 U11.3 | length 84.3
  Top Layer w12: U11.3@2181.99,2543.31 2182.09,2543.41 2197.93,2543.41 2205.9,2551.38 R43.1@2227.99,2551.38 R45.2@2262.99,2551.38
FDA_3V3: C29.3 C32.2 C33.2 R98.1 R102.2 R122.1 R126.2 | length 120
  Bottom Layer w18: v1(1583.59,994.11) R126.2@1613.59,994.11 ; v1(1583.59,1874.88) R102.2@1613.59,1874.88 ; v1(1797.61,555.87) R122.1@1827.61,555.87 ; v1(1798.59,1436.63) R98.1@1828.59,1436.63
  other v1: 1936.05,2403.8 1956.05,2403.8 1976.05,2403.8 1936.05,2423.8 1956.05,2423.8 1976.05,2423.8
FMC_1.8V: J1.G39 J1.H40 R30.2 R40.1 | length 60
  Top Layer w18: v1(1983.11,2277.13) R30.2@2013.11,2277.13 ; v1(2323.11,2567.13) R40.1@2353.11,2567.13
  other v1: 3538.19,383.27 3588.19,433.27
FMC_3.3V: J1.C39 J1.D32 J1.D36 J1.D38 J1.D40 R39.2 | length 30
  Top Layer w18: v1(2323.11,2456.89) R39.2@2353.11,2456.89
  other v1: 3738.19,383.27 3788.19,433.27 3738.19,483.27 3738.19,583.27 3738.19,783.27
FMC_12V: J1.C35 J1.C37 SW1.3
  other v1: 3788.19,533.27 3788.19,633.27
FMC_DCLKIN: J1.K16 R83.2 | length 1063.5
  Bottom Layer w9.5: v1(2810.63,2275) 2825,2275 2850,2250 2850,1995 3261.73,1583.27 v1(3438.19,1583.27)
FMC_O\E\N\: J1.H29 R80.2 | length 1024.2
  Top Layer w6: v1(2747.56,683.84) 2786.93,644.47 3378.69,644.47 3564.55,830.32 3564.55,906.91 v1(3538.19,933.27)
FMC_RESET: J1.G28 R9.1 | length 3242.2
  Top Layer w6: R9.1@898.87,1219.92 v1(933.87,1219.92)
  Bottom Layer w6: v1(933.87,1219.92) 975.08,1219.92 1110.12,1084.88 1793.85,1084.88 1907.96,1198.99 2754.25,1198.99 2907.18,1351.91 2969.9,1351.91 3000,1321.81 3000,1060.87 3021.54,1039.34 3349.31,1039.34 3364.85,1054.87 3597.13,1054.87 3609.79,1042.22 3609.79,1036.67 3613.18,1033.27 3613.18,1008.27 v1(3588.19,983.27)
